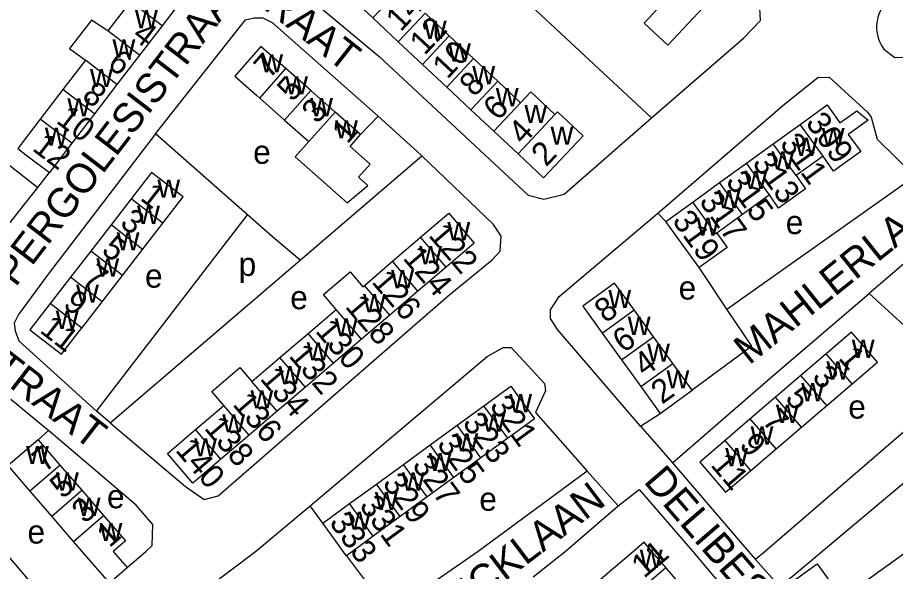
# Model space of a CAD drawing. Extents: x 159045 to 160918, y 380454 to 382516.
# Drawn here: x 159269.8 to 159418.5, y 381496.6 to 381590.5 of the extents above; entities that cross this region are included whole.
import ezdxf

# ---------------------------------------------------------------- set-up
doc = ezdxf.new("R2010")
doc.units = 0
for name, color, linetype in [('BLT_Basislijn', 7, 'Continuous'), ('BLT_Bebouwing', 7, 'Continuous'), ('BLT_Centroide', 7, 'Continuous'), ('BLT_Huisnummer', 7, 'Continuous'), ('BLT_Huisnummer_ tussenligend', 7, 'Continuous'), ('BLT_Onderverdeling_panden', 7, 'Continuous'), ('BLT_Straatnaam', 7, 'Continuous')]:
    doc.layers.add(name, color=color, linetype=linetype)

msp = doc.modelspace()

# ---------------------------------------------------------------- linework, layer by layer
at = {"layer": 'BLT_Basislijn'}
for p, q in [((159377.21, 381573.49), (159327.24, 381620.01)), ((159255.22, 381575.7), (159273.23, 381561.69)), ((159330.91, 381573.77), (159327.91, 381570.66)), ((159308.73, 381557.02), (159293.18, 381570.79)), ((159317.67, 381549.37), (159338.26, 381567.05)), ((159273.23, 381561.69), (159275.19, 381564.2)), ((159389.94, 381541.08), (159421.82, 381563.62)), ((159267.23, 381554.09), (159273.23, 381561.69)), ((159283.18, 381523.77), (159308.73, 381557.02)), ((159313, 381553.29), (159308.73, 381557.02)), ((159379.62, 381555.91), (159378.26, 381557.33)), ((159429.14, 381556.71), (159414.07, 381543.7)), ((159317.67, 381549.37), (159313, 381553.29)), ((159285.51, 381521.77), (159317.67, 381549.37)), ((159389.94, 381541.08), (159385.28, 381548.1)), ((159397.76, 381529.74), (159414.07, 381543.7)), ((159430.1, 381529.05), (159414.07, 381543.7)), ((159394.16, 381534.77), (159389.94, 381541.08)), ((159394.16, 381534.77), (159384.08, 381527.31)), ((159380.76, 381515.02), (159397.76, 381529.74)), ((159375.34, 381521.25), (159378.68, 381523.4)), ((159375.34, 381521.25), (159380.76, 381515.02)), ((159273.29, 381518.93), (159275.02, 381520.49)), ((159371.56, 381507.73), (159366.3, 381513.6)), ((159321.49, 381504.79), (159319.38, 381507.75)), ((159325.5, 381499.28), (159332.85, 381489.54)), ((159398.94, 381493.99), (159394.83, 381498.62))]:
    msp.add_line(p, q, dxfattribs=at)
for points in [[(159377.21, 381573.49), (159392.79, 381586.98), (159395.66, 381589.97), (159395.47, 381593.16), (159345.49, 381639.74), (159345.35, 381639.87)], [(159309.98, 381601.47), (159310.09, 381601.38), (159331.07, 381583.88), (159356.27, 381560.36), (159358.96, 381559.69), (159362.39, 381560.56), (159377.21, 381573.49)], [(159416.45, 381592.46), (159416.08, 381591.86), (159415.77, 381591.22), (159415.55, 381590.55), (159415.4, 381589.86), (159415.32, 381589.16), (159415.33, 381588.45), (159415.42, 381587.75), (159415.58, 381587.06), (159415.83, 381586.39), (159416.14, 381585.76), (159416.55, 381585.13)], [(159293.18, 381570.79), (159308.39, 381590.08), (159309.87, 381590.41), (159311.35, 381590.43), (159312.94, 381589.66), (159330.91, 381573.77)], [(159416.55, 381585.13), (159418.4, 381583.69), (159420.62, 381583.74), (159440.44, 381564.95), (159441.06, 381562.69), (159471.12, 381533.65)], [(159378.26, 381557.33), (159399.76, 381575.88), (159405.39, 381580.31), (159407.3, 381580.4), (159413.8, 381574.42), (159414.39, 381573.6), (159415.42, 381569.87), (159421.82, 381563.62)], [(159338.26, 381567.05), (159338.17, 381567.13), (159330.91, 381573.77)], [(159293.18, 381570.79), (159274.99, 381546.98), (159269.94, 381540.16), (159269.24, 381538.67), (159269.37, 381537.37), (159270.01, 381535.68), (159283.18, 381523.77)], [(159285.51, 381521.77), (159298.27, 381511), (159301.4, 381508.81), (159303.78, 381509.42), (159342.74, 381543.31), (159350.21, 381549.42), (159351.58, 381550.86), (159351.74, 381553.41), (159350.4, 381555.41), (159338.26, 381567.05)], [(159375.34, 381521.25), (159361.28, 381537.59), (159360.07, 381539.48), (159360.07, 381540.94), (159361.55, 381543.2), (159378.26, 381557.33)], [(159319.38, 381507.75), (159349.35, 381533.02), (159352.06, 381534.58), (159353.39, 381534.58), (159359.06, 381528.44), (159359.21, 381527.23), (159357.55, 381523.54), (159366.3, 381513.6)], [(159430.1, 381529.05), (159396.43, 381500), (159394.83, 381498.62)], [(159275.02, 381520.49), (159274.53, 381520.9), (159268.65, 381525.77)], [(159398.94, 381493.99), (159435.13, 381524.38)], [(159285.51, 381521.77), (159285.41, 381521.85), (159283.18, 381523.77)], [(159288.37, 381497.3), (159291.53, 381500), (159292.59, 381501), (159292.74, 381504.59), (159289.88, 381507.86), (159275.02, 381520.49)], [(159380.76, 381515.02), (159393.6, 381500), (159394.83, 381498.62)], [(159366.3, 381513.6), (159347.85, 381500), (159333.33, 381489.92), (159332.85, 381489.54)], [(159371.56, 381507.73), (159375.08, 381510.5), (159384.2, 381500), (159401.09, 381479.87), (159401.54, 381479.32)], [(159316.4, 381470.04), (159316.09, 381470.39), (159300.62, 381488.14), (159300.3, 381491.32), (159302.11, 381493.96), (159310.09, 381500), (159319.38, 381507.75)], [(159357.13, 381495.72), (159362.55, 381500), (159371.56, 381507.73)], [(159277.67, 381488.14), (159267.6, 381500), (159263.82, 381504.44), (159263.66, 381504.63)]]:
    msp.add_lwpolyline(points, dxfattribs=at)
at = {"layer": 'BLT_Bebouwing'}
for p, q in [((159298.09, 381594.08), (159294.28, 381589.1)), ((159288.92, 381593.21), (159285.1, 381588.22)), ((159326.09, 381594.05), (159329.99, 381590.41)), ((159342.94, 381587.37), (159338.84, 381591.22)), ((159329.99, 381590.41), (159334.3, 381586.37)), ((159294.28, 381589.1), (159290.46, 381584.12)), ((159347.05, 381583.53), (159342.94, 381587.37)), ((159334.3, 381586.37), (159338.4, 381582.53)), ((159290.46, 381584.12), (159286.64, 381579.14)), ((159281.29, 381583.24), (159277.47, 381578.26)), ((159338.4, 381582.53), (159342.51, 381578.68)), ((159351.15, 381579.68), (159347.05, 381583.53)), ((159319.47, 381578.11), (159315.25, 381581.83)), ((159355.02, 381576.05), (159351.15, 381579.68)), ((159277.47, 381578.26), (159273.65, 381573.28)), ((159286.64, 381579.14), (159282.83, 381574.16)), ((159323.59, 381574.47), (159319.47, 381578.11)), ((159342.51, 381578.68), (159346.61, 381574.84)), ((159310.82, 381576.82), (159315.04, 381573.09)), ((159346.61, 381574.84), (159350.49, 381571.21)), ((159282.83, 381574.16), (159279.01, 381569.18)), ((159327.91, 381570.66), (159323.59, 381574.47)), ((159315.04, 381573.09), (159319.16, 381569.46)), ((159397.82, 381569.09), (159402.37, 381572.38)), ((159350.49, 381571.21), (159354.59, 381567.37)), ((159279.01, 381569.18), (159275.19, 381564.2)), ((159393.27, 381565.79), (159397.82, 381569.09)), ((159406.27, 381566.99), (159401.72, 381563.7)), ((159388.72, 381562.5), (159393.27, 381565.79)), ((159384.17, 381559.21), (159388.72, 381562.5)), ((159397.17, 381560.41), (159392.62, 381557.11)), ((159289.07, 381559.78), (159285.63, 381555.34)), ((159379.62, 381555.91), (159384.17, 381559.21)), ((159392.62, 381557.11), (159388.26, 381553.96)), ((159290.99, 381551.19), (159294.43, 381555.63)), ((159285.63, 381555.34), (159282.19, 381550.9)), ((159333.31, 381549.17), (159338.08, 381553.24)), ((159287.55, 381546.75), (159290.99, 381551.19)), ((159282.19, 381550.9), (159278.75, 381546.46)), ((159328.55, 381545.09), (159333.31, 381549.17)), ((159342.39, 381548.19), (159337.62, 381544.12)), ((159284.11, 381542.31), (159287.55, 381546.75)), ((159278.75, 381546.46), (159275.31, 381542.02)), ((159337.62, 381544.12), (159332.86, 381540.05)), ((159280.67, 381537.86), (159284.11, 381542.31)), ((159319.02, 381536.95), (159323.78, 381541.02)), ((159377.51, 381536.39), (159374.23, 381540.93)), ((159332.86, 381540.05), (159328.09, 381535.98)), ((159314.25, 381532.88), (159319.02, 381536.95)), ((159368.82, 381537.01), (159372.11, 381532.47)), ((159328.09, 381535.98), (159323.32, 381531.91)), ((159406.79, 381533.51), (159402.51, 381529.84)), ((159309.48, 381528.81), (159314.25, 381532.88)), ((159323.32, 381531.91), (159318.56, 381527.83)), ((159372.11, 381532.47), (159375.39, 381527.93)), ((159384.08, 381527.31), (159380.8, 381531.85)), ((159402.51, 381529.84), (159398.22, 381526.16)), ((159318.56, 381527.83), (159313.79, 381523.76)), ((159375.39, 381527.93), (159378.68, 381523.4)), ((159378.68, 381523.4), (159384.08, 381527.31)), ((159406.88, 381524.73), (159411.17, 381528.4)), ((159398.22, 381526.16), (159393.93, 381522.49)), ((159299.95, 381520.66), (159304.72, 381524.73)), ((159344.26, 381521.38), (159348.81, 381524.69)), ((159402.6, 381521.06), (159406.88, 381524.73)), ((159313.79, 381523.76), (159309.02, 381519.69)), ((159339.71, 381518.06), (159344.26, 381521.38)), ((159393.93, 381522.49), (159389.65, 381518.82)), ((159398.31, 381517.39), (159402.6, 381521.06)), ((159273.29, 381518.93), (159268.2, 381514.54)), ((159273.29, 381518.93), (159276.98, 381514.65)), ((159309.02, 381519.69), (159304.26, 381515.62)), ((159352.83, 381519.18), (159348.28, 381515.86)), ((159335.15, 381514.74), (159339.71, 381518.06)), ((159394.02, 381513.72), (159398.31, 381517.39)), ((159348.28, 381515.86), (159343.72, 381512.54)), ((159271.9, 381510.25), (159268.2, 381514.54)), ((159276.98, 381514.65), (159280.68, 381510.36)), ((159330.6, 381511.42), (159335.15, 381514.74)), ((159343.72, 381512.54), (159339.17, 381509.23)), ((159326.05, 381508.11), (159330.6, 381511.42)), ((159275.6, 381505.97), (159271.9, 381510.25)), ((159280.68, 381510.36), (159284.38, 381506.08)), ((159321.49, 381504.79), (159326.05, 381508.11)), ((159339.17, 381509.23), (159334.62, 381505.91)), ((159279.3, 381501.69), (159275.6, 381505.97)), ((159334.62, 381505.91), (159330.06, 381502.59)), ((159383.27, 381492.98), (159379.61, 381497.27))]:
    msp.add_line(p, q, dxfattribs=at)
for points in [[(159382.84, 381596.88), (159386.83, 381593.14), (159379.94, 381585.79), (159375.95, 381589.52), (159378.23, 381591.96)], [(159285.1, 381588.22), (159282.3, 381590.05), (159278.62, 381585.24), (159281.29, 381583.24)], [(159315.25, 381581.83), (159311.03, 381585.56), (159306.6, 381580.54), (159310.35, 381577.24), (159310.82, 381576.82)], [(159360.84, 381574.04), (159356.73, 381577.88), (159355.02, 381576.05)], [(159402.37, 381572.38), (159406.92, 381575.67), (159409.12, 381572.64), (159411.95, 381574.69), (159413.87, 381573.1), (159410.53, 381570.68), (159412.63, 381567.79), (159408.04, 381564.47), (159406.27, 381566.99)], [(159273.65, 381573.28), (159269.84, 381568.3), (159271.22, 381567.24), (159275.19, 381564.2)], [(159354.59, 381567.37), (159358.92, 381563.31), (159365.61, 381570.46), (159361.28, 381574.52), (159360.84, 381574.04)], [(159319.16, 381569.46), (159316.82, 381566.86), (159325.66, 381559.06), (159329.12, 381562.03), (159327.56, 381563.45), (159329.52, 381565.61), (159326.12, 381568.63), (159327.91, 381570.66)], [(159294.43, 381555.63), (159297.87, 381560.07), (159296.46, 381561.16), (159292.51, 381564.22), (159289.07, 381559.78)], [(159401.72, 381563.7), (159403.25, 381561.44), (159398.7, 381558.15), (159397.17, 381560.41)], [(159338.08, 381553.24), (159342.84, 381557.3), (159347.15, 381552.26), (159342.39, 381548.19)], [(159385.28, 381548.1), (159382.55, 381551.86), (159379.62, 381555.91)], [(159388.26, 381553.96), (159390.02, 381551.53), (159385.28, 381548.1)], [(159323.78, 381541.02), (159321.62, 381543.55), (159326.12, 381547.4), (159328.29, 381544.87), (159328.55, 381545.09)], [(159374.23, 381540.93), (159370.94, 381545.46), (159365.53, 381541.55), (159368.82, 381537.01)], [(159275.31, 381542.02), (159271.87, 381537.58), (159277.23, 381533.43), (159280.3, 381537.38), (159280.67, 381537.86)], [(159380.8, 381531.85), (159377.51, 381536.39)], [(159411.17, 381528.4), (159415.45, 381532.07), (159414.32, 381533.38), (159411.07, 381537.17), (159406.79, 381533.51)], [(159304.72, 381524.73), (159302.69, 381527.09), (159307.43, 381531.16), (159309.48, 381528.81)], [(159348.81, 381524.69), (159353.36, 381528), (159357.38, 381522.49), (159353.34, 381519.55), (159352.83, 381519.18)], [(159304.26, 381515.62), (159299.49, 381511.55), (159295.18, 381516.59), (159299.95, 381520.66)], [(159389.65, 381518.82), (159385.36, 381515.15), (159389.74, 381510.04), (159393.54, 381513.3), (159394.02, 381513.72)], [(159284.38, 381506.08), (159288.08, 381501.8), (159285.99, 381500), (159288.37, 381497.3)], [(159325.5, 381499.28), (159324.98, 381500), (159324.44, 381500.75), (159321.49, 381504.79)], [(159330.06, 381502.59), (159326.51, 381500), (159325.5, 381499.28)], [(159285.35, 381494.71), (159283.01, 381497.41), (159280.75, 381500), (159279.3, 381501.69)], [(159379.61, 381497.27), (159377.27, 381500), (159375.94, 381501.56), (159374.12, 381500), (159370.79, 381497.15), (159368.1, 381494.84), (159371.78, 381490.53), (159374.45, 381492.86)], [(159285.35, 381494.71), (159288.37, 381497.3)]]:
    msp.add_lwpolyline(points, dxfattribs=at)
msp.add_lwpolyline([(159408.79, 381483.21), (159400.62, 381494.55), (159405.27, 381497.9), (159409.46, 381492.09), (159438.77, 381513.23), (159445.67, 381503.66), (159413.52, 381480.47), (159410.62, 381484.5)], close=True, dxfattribs=at)
at = {"layer": 'BLT_Onderverdeling_panden'}
for p, q in [((159329.99, 381590.41), (159334.52, 381595.25)), ((159294.28, 381589.1), (159288.92, 381593.21)), ((159334.3, 381586.37), (159338.84, 381591.22)), ((159290.46, 381584.12), (159285.1, 381588.22)), ((159338.4, 381582.53), (159342.94, 381587.37)), ((159286.64, 381579.14), (159281.29, 381583.24)), ((159342.51, 381578.68), (159347.05, 381583.53)), ((159310.82, 381576.82), (159315.25, 381581.83)), ((159346.61, 381574.84), (159351.15, 381579.68)), ((159282.83, 381574.16), (159277.47, 381578.26)), ((159315.04, 381573.09), (159319.47, 381578.11)), ((159350.49, 381571.21), (159355.02, 381576.05)), ((159279.01, 381569.18), (159273.65, 381573.28)), ((159319.16, 381569.46), (159323.59, 381574.47)), ((159354.59, 381567.37), (159360.84, 381574.04)), ((159406.27, 381566.99), (159402.37, 381572.38)), ((159401.72, 381563.7), (159397.82, 381569.09)), ((159397.17, 381560.41), (159393.27, 381565.79)), ((159392.62, 381557.11), (159388.72, 381562.5)), ((159294.43, 381555.63), (159289.07, 381559.78)), ((159290.99, 381551.19), (159285.63, 381555.34)), ((159342.39, 381548.19), (159338.08, 381553.24)), ((159287.55, 381546.75), (159282.19, 381550.9)), ((159337.62, 381544.12), (159333.31, 381549.17)), ((159284.11, 381542.31), (159278.75, 381546.46)), ((159332.86, 381540.05), (159328.55, 381545.09)), ((159280.67, 381537.86), (159275.31, 381542.02)), ((159328.09, 381535.98), (159323.78, 381541.02)), ((159368.82, 381537.01), (159374.23, 381540.93)), ((159323.32, 381531.91), (159319.02, 381536.95)), ((159372.11, 381532.47), (159377.51, 381536.39)), ((159411.17, 381528.4), (159406.79, 381533.51)), ((159318.56, 381527.83), (159314.25, 381532.88)), ((159375.39, 381527.93), (159380.8, 381531.85)), ((159313.79, 381523.76), (159309.48, 381528.81)), ((159406.88, 381524.73), (159402.51, 381529.84)), ((159402.6, 381521.06), (159398.22, 381526.16)), ((159309.02, 381519.69), (159304.72, 381524.73)), ((159352.83, 381519.18), (159348.81, 381524.69)), ((159348.28, 381515.86), (159344.26, 381521.38)), ((159398.31, 381517.39), (159393.93, 381522.49)), ((159304.26, 381515.62), (159299.95, 381520.66)), ((159394.02, 381513.72), (159389.65, 381518.82)), ((159343.72, 381512.54), (159339.71, 381518.06)), ((159271.9, 381510.25), (159276.98, 381514.65)), ((159339.17, 381509.23), (159335.15, 381514.74)), ((159334.62, 381505.91), (159330.6, 381511.42)), ((159275.6, 381505.97), (159280.68, 381510.36)), ((159330.06, 381502.59), (159326.05, 381508.11)), ((159279.3, 381501.69), (159284.38, 381506.08)), ((159374.45, 381492.86), (159379.61, 381497.27))]:
    msp.add_line(p, q, dxfattribs=at)
msp.add_lwpolyline([(159388.26, 381553.96), (159388.07, 381553.82), (159384.17, 381559.21)], dxfattribs=at)

# ---------------------------------------------------------------- texts
at = {"layer": 'BLT_Centroide'}
for s, p in [('w', (159289.69, 381588.66)), ('w', (159338.62, 381586.86)), ('w', (159285.88, 381583.69)), ('w', (159342.72, 381583.02)), ('w', (159310.92, 381581.19)), ('w', (159346.83, 381579.17)), ('w', (159282.06, 381578.69)), ('w', (159315.14, 381577.47)), ('w', (159350.81, 381575.45)), ('w', (159278.23, 381573.72)), ('w', (159319.36, 381573.75)), ('w', (159355.66, 381572.61)), ('w', (159274.42, 381568.75)), ('w', (159323.59, 381570)), ('w', (159360.09, 381568.91)), ('w', (159406.04, 381568.67)), ('e', (159309.71, 381565.69)), ('w', (159401.5, 381567.03)), ('w', (159397.5, 381564.75)), ('w', (159392.94, 381561.45)), ('w', (159293.48, 381559.94)), ('w', (159388.39, 381558.16)), ('w', (159290.04, 381555.5)), ('e', (159399.93, 381553.78)), ('w', (159342.61, 381552.75)), ('w', (159384.81, 381553.52)), ('w', (159286.59, 381551.03)), ('w', (159337.84, 381548.67)), ('w', (159283.15, 381546.59)), ('p', (159307.25, 381546.69)), ('e', (159291.39, 381544.7)), ('w', (159333.08, 381544.61)), ('w', (159279.71, 381542.16)), ('e', (159381.79, 381542.69)), ('e', (159315.99, 381541.05)), ('w', (159328.31, 381540.55)), ('w', (159369.88, 381541.25)), ('w', (159276.27, 381537.72)), ('w', (159323.55, 381536.45)), ('w', (159373.16, 381536.69)), ('w', (159318.78, 381532.39)), ('w', (159376.45, 381532.16)), ('w', (159411.12, 381532.8)), ('w', (159406.83, 381529.12)), ('w', (159314.02, 381528.33)), ('w', (159379.73, 381527.62)), ('w', (159309.25, 381524.25)), ('w', (159402.55, 381525.45)), ('w', (159353.09, 381523.59)), ('w', (159398.27, 381521.78)), ('e', (159410.52, 381522.52)), ('w', (159304.48, 381520.17)), ('w', (159348.55, 381520.28)), ('w', (159343.98, 381516.97)), ('w', (159393.98, 381518.11)), ('w', (159299.72, 381516.11)), ('w', (159271.24, 381514.81)), ('w', (159389.69, 381514.44)), ('w', (159339.44, 381513.64)), ('w', (159276.3, 381510.31)), ('w', (159334.89, 381510.31)), ('e', (159284.95, 381507.32)), ('w', (159330.33, 381507)), ('e', (159348.02, 381506.89)), ('w', (159279.98, 381506.03)), ('w', (159325.78, 381503.69)), ('e', (159271.48, 381501.34)), ('w', (159283.69, 381501.75)), ('w', (159375.2, 381497.22))]:
    msp.add_text(s, height=4, dxfattribs=at).set_placement(p)
at = {"layer": 'BLT_Huisnummer'}
for s, rotation, p in [('14', 46.8799, (159334.71, 381587.94)), ('10', 46.8799, (159342.61, 381579.9)), ('6', 322.5391, (159284.83, 381582.23)), ('7', 48.5658, (159312.46, 381579.95)), ('6', 46.8803, (159351.2, 381572.84)), ('309', 305.9013, (159403.17, 381572.63)), ('1', 48.5682, (159325.66, 381568.93)), ('12', 322.5411, (159272.12, 381568.08)), ('2', 46.8795, (159359.35, 381565.05)), ('313', 305.9013, (159394.14, 381565.8)), ('1', 322.2325, (159290.4, 381559.68)), ('319', 305.9027, (159380.58, 381556.02)), ('122', 310.5048, (159339.27, 381553.52)), ('5', 322.231, (159283.83, 381550.7)), ('126', 310.5113, (159329.65, 381545.62)), ('8', 35.903, (159369.4, 381538.6)), ('11', 322.2295, (159273.38, 381537.24)), ('130', 310.5057, (159320.1, 381537.29)), ('1', 310.5856, (159408.72, 381532.7)), ('134', 310.5057, (159310.74, 381529.21)), ('2', 35.903, (159378.97, 381524.84)), ('5', 310.5921, (159399.67, 381525.87)), ('321', 306.0755, (159349.64, 381524.66)), ('325', 306.0706, (159340.71, 381518.15)), ('140', 310.5067, (159296.39, 381517.11)), ('7', 40.813, (159274.43, 381513.26)), ('11', 310.5865, (159387.06, 381514.6)), ('329', 306.0706, (159331.49, 381511.52)), ('333', 306.0746, (159322.48, 381504.89)), ('1', 40.9444, (159285.37, 381500.53)), ('11', 40.4868, (159375.92, 381495.33))]:
    msp.add_text(s, height=4, rotation=rotation, dxfattribs=at).set_placement(p)
at = {"layer": 'BLT_Huisnummer_ tussenligend'}
for s, rotation, p in [('12', 46.8799, (159338.75, 381583.94)), ('4', 322.5324, (159289.02, 381587.06)), ('8', 46.8803, (159347.17, 381576.87)), ('8', 322.5391, (159280.49, 381576.8)), ('5', 48.5682, (159316.37, 381576.04)), ('3', 48.5682, (159320.55, 381572.31)), ('10', 322.5391, (159276.17, 381572.76)), ('4', 46.8795, (159355.46, 381568.76)), ('311', 305.9013, (159398.8, 381569.08)), ('315', 305.9013, (159389.64, 381562.7)), ('317', 305.9013, (159385.14, 381559.3)), ('3', 322.2325, (159286.95, 381555.3)), ('124', 310.5048, (159334.93, 381549.65)), ('7', 322.231, (159280.72, 381545.9)), ('9', 322.231, (159277.32, 381541.55)), ('128', 310.5113, (159325.16, 381541.43)), ('6', 35.903, (159372.45, 381533.52)), ('132', 310.5057, (159315.61, 381533.09)), ('4', 35.903, (159376.02, 381529.48)), ('3', 310.5856, (159404.24, 381529.48)), ('136', 310.5057, (159306.09, 381524.87)), ('7', 310.5921, (159395.79, 381522.01)), ('323', 306.0755, (159345.04, 381521.77)), ('138', 310.5057, (159301.29, 381520.83)), ('9', 310.5921, (159391.92, 381517.97)), ('327', 306.0706, (159336.52, 381514.59)), ('5', 40.9444, (159277.44, 381508.77)), ('331', 306.0706, (159327.57, 381507.74)), ('3', 40.9444, (159281.16, 381504.58))]:
    msp.add_text(s, height=4, rotation=rotation, dxfattribs=at).set_placement(p)
at = {"layer": 'BLT_Straatnaam'}
for s, height, rotation, p in [('CHAUSSONSTRAAT', 5, 321.7075, (159274.82, 381620.86)), ('PERGOLESISTRAAT', 5, 52.4102, (159269.46, 381544.67)), ('MAHLERLAAN', 5, 38.7082, (159393.73, 381531.49)), ('SCARLATTISTRAAT', 4.9999, 322.2307, (159232.37, 381555.74)), ('DELIBESWEG', 5, 310.792, (159375.7, 381511.8)), ('GLUCKLAAN', 5, 37.2188, (159337.48, 381483.6))]:
    msp.add_text(s, height=height, rotation=rotation, dxfattribs=at).set_placement(p)

doc.saveas('drawing.dxf')
